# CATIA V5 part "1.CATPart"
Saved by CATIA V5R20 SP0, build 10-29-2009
Part number: 1
Bounding box of the stored display mesh (mm): x -84.677 to 84.677, y -75 to 108, z 0 to 94
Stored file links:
  E:\Ehsan\Amoozesh\CATIA\CATIA Course\Advanced\Videos\Session-19\1.CATPart
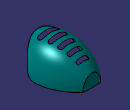
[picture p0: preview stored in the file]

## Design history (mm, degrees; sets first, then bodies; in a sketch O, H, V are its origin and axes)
AxisSystem1: origin (0, 0, 0), X (1, 0, 0), Y (0, 1, 0), Z (0, 0, 1)
Set1 "Sketchers"
  Sketch1 on XY plane of AxisSystem1, origin (0, 0, 0), H (0, 1, 0), V (-1, 0, 0)
    point P1 (-75, 0)
    construction line L1 (-75, 0) -> (108, 0)
    construction line L2 (108, 0) -> (108, 85)
    construction line L3 (108, 85) -> (-75, 85)
    construction line L4 (-75, 85) -> (-75, 0)
    point P2 (108, 0)
    reference intersected line E1 through (0, 0) direction (0, 1) from ZX plane of AxisSystem1
    arc A1 centre (-19.3774, -90) radius 175 from (108, 30) to (-75, 75.9251) ccw
    point P6 (108, 30)
    point P7 (-75, 75.9251)
    distance L2 E1 = 108
    length L3 = 183
    length L2 = 85
    distance P6 P2 = 30
    radius A1 = 175
    coincidence: P1 H, P6 L2, P7 L4
    horizontal: L1 H, L3 H
    vertical: L2 V, L4 V
    tangency: A1 L3
  Sketch2 on YZ plane of AxisSystem1, origin (0, 0, 0), H (0, 1, 0), V (0, 0, 1)
    point P1 (-75, 0)
    construction line L1 (-75, 0) -> (108, 0)
    construction line L2 (108, 0) -> (108, 94)
    construction line L3 (108, 94) -> (-75, 94)
    construction line L4 (-75, 94) -> (-75, 0)
    point P2 (108, 0)
    reference intersected line E1 through (0, 0) direction (0, 1) from ZX plane of AxisSystem1
    arc A1 centre (-15.4868, -81) radius 175 from (108, 43) to (-75, 83.5697) ccw
    point P6 (108, 43)
    point P7 (-75, 83.5697)
    distance L2 E1 = 108
    length L3 = 183
    length L2 = 94
    distance P6 P2 = 43
    radius A1 = 175
    coincidence: P1 H, P6 L2, P7 L4
    horizontal: L1 H, L3 H
    vertical: L2 V, L4 V
    tangency: A1 L3
Set2 "Curves"
  Symmetry1: ToTransfor Sketch1, Reference YZ plane of AxisSystem1
Set3 "Planes"
  Plane1: type OffsetPt, RefPlane ZX plane of AxisSystem1, RefPoint Sketch2.P6
  Sketch3 on Plane1, origin (0, 108, 0), H (-1, 0, 0), V (0, 0, 1)
    reference projected point E3 (0, 43) from Sketch2.P6
    ellipse A1 centre (0, 0) semi-axes 30, 43 rotation 0 from (30, 0) to (-30, 0)
    construction line L1 (-30, 0) -> (30, 0)
    coincidence: A1 E3
    horizontal: L1 H
Set4 "Surfaces"
  Loft1: Sections (Sketch1; Sketch2; Symmetry1), Guides Sketch3
  Sketch4 on YZ plane of AxisSystem1, origin (0, 0, 0), H (0, 1, 0), V (0, 0, 1)
    arc A1 centre (0, 31) radius 31 from (-28.5133, 18.8348) to (0, 0) ccw
    point P1 (0, 31)
    arc A2 centre (-196.8338, -52.9789) radius 183 from (-28.5133, 18.8348) to (-75, 83.5697) ccw
    projected line E1 (108, 0) -> (-75, 0) from edge of Symmetry1
    reference projected point E2 (-75, 83.5697) from Sketch2.P7
    line L1 (0, 0) -> (108, 0)
    radius A1 = 31
    radius A2 = 183
    tangency: A1 E1, A2 A1
    coincidence: A2 E2, P1 V
  Extrude1: Lim1 100, Lim2 100, Element1 Sketch4
  Extrapol1: ToExtrapol edge of Extrude1, Support Extrude1, Length 10
  Split1: ToCut Loft1, Cutting Extrapol1
  Line1: type PtPt, FirstPoint vertex of Symmetry1, SecondPoint Sketch1.P6
  Fill1: Boundary (Line1; Sketch3)
  Sketch5 on XY plane of AxisSystem1, origin (0, 0, 0), H (-1, 0, 0), V (0, -1, 0)
    construction line L1 (-25, 40) -> (25, 40)
    point P1 (-25, 40)
    point P2 (25, 40)
    line L2 (-25, 49) -> (25, 49)
    line L3 (25, 31) -> (-25, 31)
    arc A1 centre (25, 40) radius 9 from (25, 49) to (25, 31) cw
    arc A2 centre (-25, 40) radius 9 from (-25, 31) to (-25, 49) cw
    point P11 (-22.5, 8)
    arc A3 centre (-22.5, 8) radius 8 from (-22.5, 0) to (-22.5, 16) cw
    point P12 (22.5, 8)
    arc A4 centre (22.5, 8) radius 8 from (22.5, 16) to (22.5, 0) cw
    line L4 (22.5, 0) -> (-22.5, 0)
    line L5 (-22.5, 16) -> (22.5, 16)
    point P17 (-20, -22)
    arc A5 centre (-20, -22) radius 7 from (-20, -29) to (-20, -15) cw
    point P18 (20, -22)
    arc A6 centre (20, -22) radius 7 from (20, -15) to (20, -29) cw
    line L6 (20, -29) -> (-20, -29)
    line L7 (-20, -15) -> (20, -15)
    point P23 (-17.5, -50)
    arc A7 centre (-17.5, -50) radius 6 from (-17.5, -56) to (-17.5, -44) cw
    point P24 (17.5, -50)
    arc A8 centre (17.5, -50) radius 6 from (17.5, -44) to (17.5, -56) cw
    line L8 (17.5, -56) -> (-17.5, -56)
    line L9 (-17.5, -44) -> (17.5, -44)
    point P29 (-15, -76)
    arc A9 centre (-15, -76) radius 5 from (-15, -81) to (-15, -71) cw
    point P30 (15, -76)
    arc A10 centre (15, -76) radius 5 from (15, -71) to (15, -81) cw
    line L10 (15, -81) -> (-15, -81)
    line L11 (-15, -71) -> (15, -71)
    distance L1 L2 = 9
    length L2 = 50
    length L5 = 45
    length L7 = 40
    length L9 = 35
    length L11 = 30
    radius A3 = 8
    radius A5 = 7
    radius A7 = 6
    radius A9 = 5
    distance L5 L3 = 15
    distance L7 L4 = 15
    distance L9 L6 = 15
    distance L11 L8 = 15
    horizontal: L1 H
    tangency: A1 L2, A2 L2, A1 L3, A2 L3, A3 L5, A4 L4, A3 L4, A4 L5, A5 L7, A6 L6, A5 L6, A6 L7, A8 L8, A7 L9, A8 L9, A7 L8, A10 L10, A9 L10, A10 L11, A9 L11
    symmetry: P2 P1 V, P12 P11 V, P18 P17 V, P24 P23 V, P30 P29 V
    coincidence: L4 H
  Project1: ToProject Sketch5, Support Split1, Direction XY plane of AxisSystem1
  Split2: ToCut Split1, Cutting Project1
  Join1: Elements (Split2; Fill1)
Body1 (main body)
